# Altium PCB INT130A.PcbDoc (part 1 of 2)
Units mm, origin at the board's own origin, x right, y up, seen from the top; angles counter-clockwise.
Board outline 103.68 x 57.35 mm, 2 copper layers (Top Layer, Bottom Layer), stack 1.575 mm thick; 110 components, 45 nets, 213 pads, 183 vias.
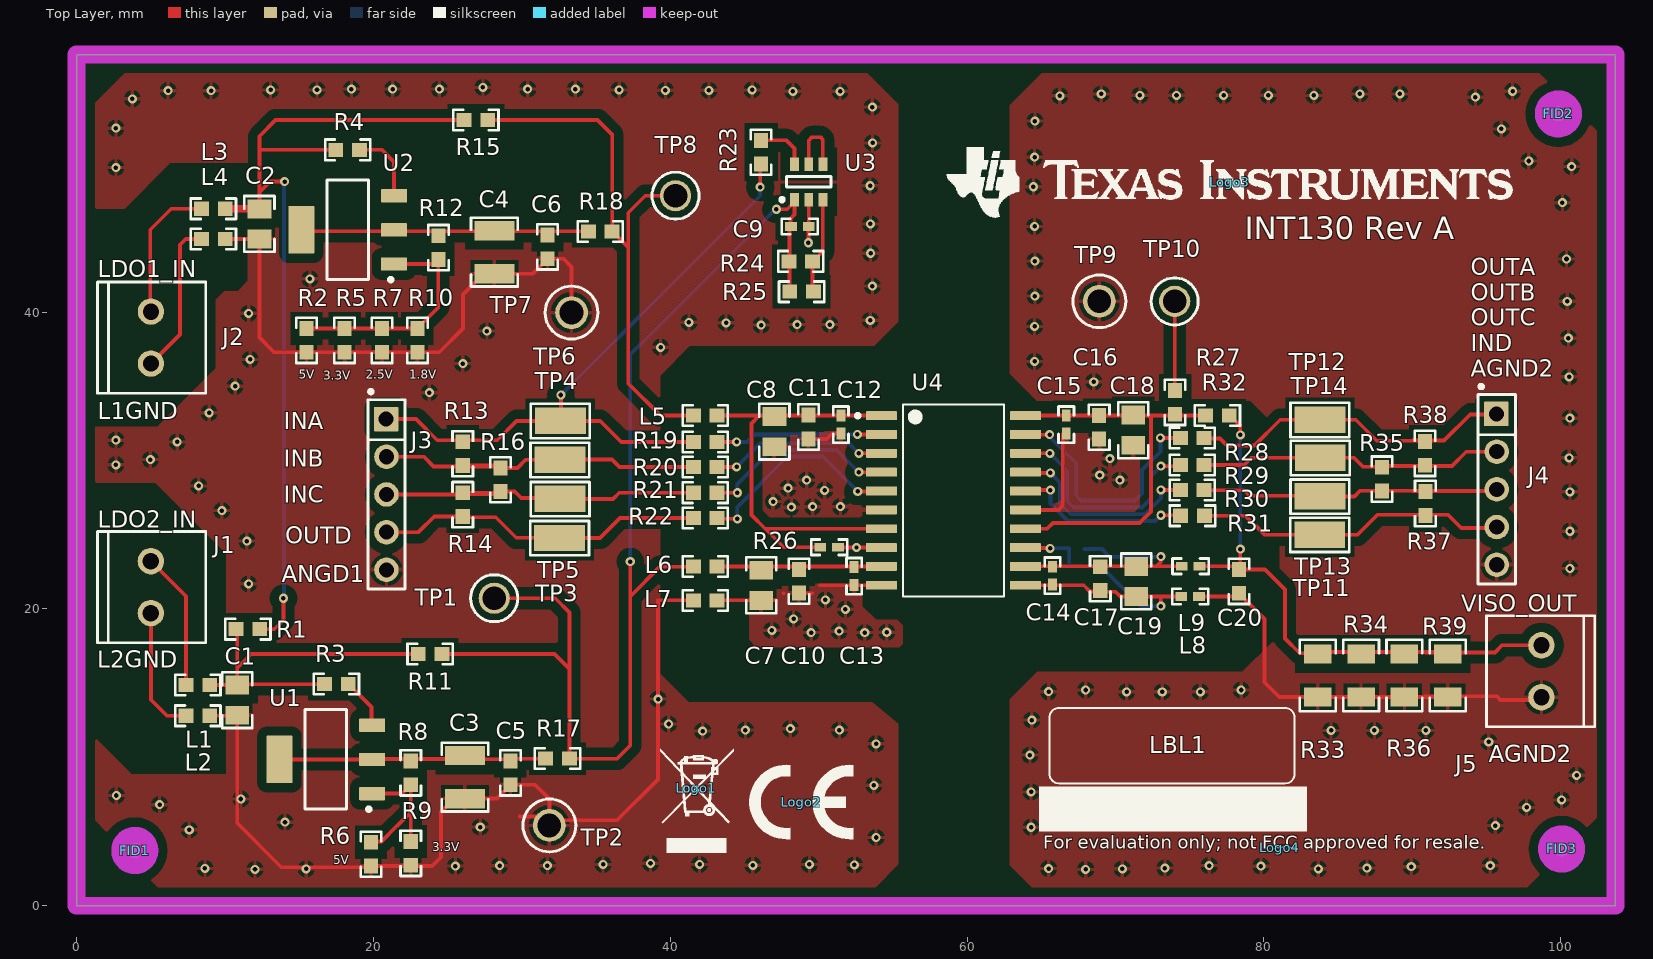
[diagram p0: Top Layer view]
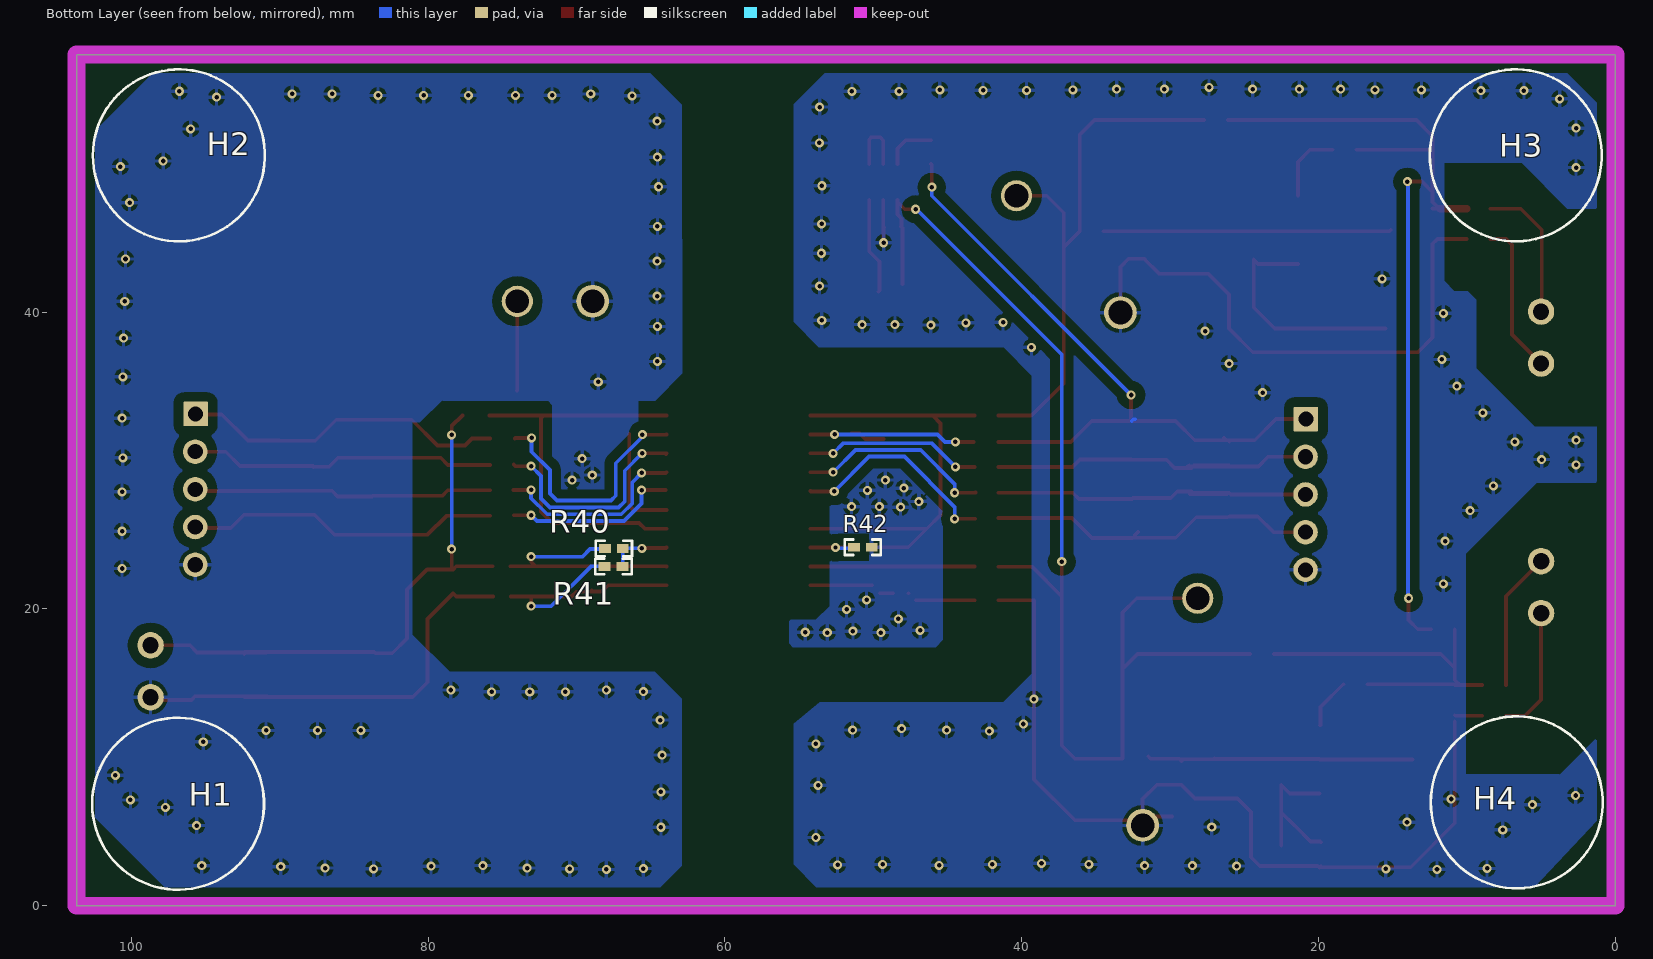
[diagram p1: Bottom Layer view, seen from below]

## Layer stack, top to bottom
Top Solder: solder mask 0.0102, Solder Resist, Dk 3.5
Top Layer: signal copper 0.0356
Dielectric1: core 1.5037, FR-4, Dk 4.8
Bottom Layer: signal copper 0.0356
Bottom Solder: solder mask 0.0102, Solder Resist, Dk 3.5

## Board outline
0,0 0,57.348 103.678,57.348 103.678,0

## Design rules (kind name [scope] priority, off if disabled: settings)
AcuteAngle [All] p1: minimum=4.50000000000000E+0001 checktracksonly=FALSE
AssemblyTestPointUsage [All] p1: valid=2
Clearance Clearance_Keepouts [((IsTrack Or IsArc) And Not InPoly) And IsFree and IsKeepOut vs ((IsTrack Or IsArc) And Not InPoly) And IsFree and IsKeepOut] p1: gap=0 ignorepadtopadclearanceinfootprint=FALSE
Clearance Clearance_BoardEdge_MountingHoles [OnCopper and InComponentClass('Mounting Holes') vs IsKeepOut] p2: gap=1.016 ignorepadtopadclearanceinfootprint=FALSE except(0: Arc-Hole Track-Hole SMDPad-Hole THPad-Hole Via-Hole Fill-Hole Poly-Hole Region-Hole Text-Hole)
Clearance Clearance_BoardEdge_Poly [OnCopper and InPoly vs IsKeepOut] p3: gap=0.635 ignorepadtopadclearanceinfootprint=FALSE except(0: Arc-Hole Track-Hole SMDPad-Hole THPad-Hole Via-Hole Fill-Hole Poly-Hole Region-Hole Text-Hole)
Clearance Clearance_BoardEdge [OnCopper and Not InComponentClass('Logo') and not InComponentClass('FiducialMark') and not InRegion(1000,500,4000,800) and Not IsKeepout vs IsKeepOut] p4: gap=0.762 ignorepadtopadclearanceinfootprint=FALSE except(0: Arc-Hole Track-Hole SMDPad-Hole THPad-Hole Via-Hole Fill-Hole Poly-Hole Region-Hole Text-Hole)
Clearance Clearance_Poly [InPolygon] p5: gap=0.635 ignorepadtopadclearanceinfootprint=FALSE except(0: Arc-Hole Track-Hole SMDPad-Hole THPad-Hole Via-Hole Fill-Hole Poly-Hole Region-Hole Text-Hole)
Clearance [All] p6: gap=0.2 ignorepadtopadclearanceinfootprint=FALSE except(0: Arc-Hole Track-Hole SMDPad-Hole THPad-Hole Via-Hole Fill-Hole Poly-Hole Region-Hole Text-Hole)
ComponentClearance ComponentClearance_MountingHoles_FiducialMarks [InComponentClass('Mounting Holes') vs InComponentClass('FiducialMark')] p1: gap=1.27 collisioncheckmode=3 verticalgap=0.254 showdistances=FALSE
ComponentClearance ComponentClearance_Shunt [InComponentClass('Header') vs InComponentClass('Shunt')] p2: gap=0 collisioncheckmode=3 verticalgap=0 showdistances=FALSE
ComponentClearance ComponentClearance_Logo [InComponentClass('Logo')] p3: gap=1.27 collisioncheckmode=3 verticalgap=0.254 showdistances=FALSE
ComponentClearance ComponentClearance_ScrewToNut [(HasFootprint('NY PMS 440 0025 PH')) vs (HasFootprint('Keystone_1902C'))] p4: gap=0.127 collisioncheckmode=3 verticalgap=0.254 showdistances=FALSE
ComponentClearance ComponentClearance_MountingHoles [InComponentClass('Mounting Holes')] p5: gap=6.35 collisioncheckmode=3 verticalgap=2540 showdistances=FALSE
ComponentClearance ComponentClearance_SmallPassives [HasFootprint('0201*') or HasFootprint('0402*') or HasFootprint('0508') or HasFootprint('0603*') or HasFootprint('0612') or HasFootprint('0805*') or HasFootprint('0815*') or HasFootprint('0830*') or HasFootprint('1206*') or HasFootprint('1210*') or HasFootprint('1808*') or HasFootprint('1812*') or HasFootprint('1825*') or HasFootprint('2010*') or HasFootprint('2220*') or HasFootprint('2225*') or HasFootprint('2512*') or HasFootprint('2728*') or HasFootprint('3518*') vs HasFootprint('0201*') or HasFootprint('0402*') or HasFootprint('0508') or HasFootprint('0603*') or HasFootprint('0612') or HasFootprint('0805*') or HasFootprint('0815*') or HasFootprint('0830*') or HasFootprint('1206*') or HasFootprint('1210*') or HasFootprint('1808*') or HasFootprint('1812*') or HasFootprint('1825*') or HasFootprint('2010*') or HasFootprint('2220*') or HasFootprint('2225*') or HasFootprint('2512*') or HasFootprint('2728*') or HasFootprint('3518*')] p6: gap=0.508 collisioncheckmode=3 verticalgap=0.254 showdistances=FALSE
ComponentClearance ComponentClearance_THtoSMT [IsThruComponent vs IsSMTComponent] p7: gap=1.016 collisioncheckmode=3 verticalgap=0.762 showdistances=FALSE
ComponentClearance ComponentClearance_THtoTH [IsThruComponent vs IsThruComponent] p8: gap=1.016 collisioncheckmode=3 verticalgap=0.762 showdistances=FALSE
ComponentClearance [All] p9: gap=1.016 collisioncheckmode=3 verticalgap=0.254 showdistances=FALSE
DiffPairsRouting [All] p1: maxlimit=2.54 minlimit=0.254 mostfreqgap=0.254 toplayer_minwidth=0.381 toplayer_maxwidth=0.381 toplayer_prefwidth=0.381 bottomlayer_minwidth=0.381 bottomlayer_maxwidth=0.381 bottomlayer_prefwidth=0.381 maxuncoupledlength=25.4
FabricationTestPointUsage TestPointUsage [All] p1: valid=2 allowmultiple=FALSE
FabricationTestpoint Testpoint [All] p1: side=3 testpointundercomponent=TRUE minsize=1.016 maxsize=2.54 preferedsize=1.524 minholesize=0 maxholesize=1.016 preferedholesize=0.813 testpointgrid=0.025 allowsidetop=TRUE allowsidebottom=TRUE usegrid=TRUE gridtolerance=0
FanoutControl Fanout_LCC [IsLCC] p1: bgadir=Out bgaviamode=Centered fanoutstyle=Auto fanoutdirection=Alternating viagrid=0.025 // Fanout_LCC (Default Rule)
FanoutControl Fanout_BGA [IsBGA] p2: bgadir=Out bgaviamode=Centered fanoutstyle=Auto fanoutdirection=Alternating viagrid=0.025 // Fanout_BGA (Default Rule)
FanoutControl Fanout_Default [All] p4: bgadir=Out bgaviamode=Centered fanoutstyle=Auto fanoutdirection=Alternating viagrid=0.025 // Fanout_Default (Default Rule)
FanoutControl Fanout_Small [(CompPinCount < 5)] p5: bgadir=Out bgaviamode=Centered fanoutstyle=Auto fanoutdirection=OutThenIn viagrid=0.025 // Fanout_Small (Default Rule)
HoleSize [All] p1: absolutevalues=TRUE maxlimit=6.375 minlimit=0.203 maxpercent=80.000 minpercent=20.000
MinimumAnnularRing MinimumAnnularRing_ThermalPadVias [IsVia and InAnyComponent] p1: minimumring=0.15
MinimumAnnularRing [All] p2: minimumring=0.152
MinimumSolderMaskSliver MinimumSolderMaskSliver_Logo [InComponentClass('Logo') vs InComponentClass('Logo')] p1: minsoldermaskwidth=0.018
MinimumSolderMaskSliver [All] p2: minsoldermaskwidth=0.1
PlaneConnect [All] p1: planeconnectstyle=Relief reliefexpansion=0.254 reliefentries=4 reliefconductorwidth=0.254 reliefairgap=0.254
PolygonConnect [All] p1: connectstyle=Relief reliefconductorwidth=0.254 reliefentries=4 polygonreliefangle="90 Angle" airgapwidth=0.254
RoutingVias ThermalPadVias [IsVia and InAnyComponent] p1: holewidth=0.305 width=0.5 viastyle="Through Hole" minholewidth=0.305 minwidth=0.483 maxholewidth=0.33 maxwidth=0.762
RoutingVias [All] p2: holewidth=0.406 width=0.864 viastyle="Through Hole" minholewidth=0.2 minwidth=0.559 maxholewidth=1.016 maxwidth=1.651
SilkToBoardRegionClearance [Not ((IsComment or IsDesignator) And (Hide <> 'False')) and not InRegion(1000,500,4000,800)] p1:
SilkToSilkClearance SilkToSilkClearance_Pb-FreeLogo [(HasFootprint('Pb-Free_Overlay_Medium') OR HasFootprint('Pb-Free_Overlay_Small')) vs (HasFootprint('Pb-Free_Overlay_Medium') OR HasFootprint('Pb-Free_Overlay_Small'))] p1: silktosilkclearance=0
SilkToSilkClearance [All] p2: silktosilkclearance=0.127
SilkToSolderMaskClearance "Silk to Solder Mask Opening" [All] p1: minsilkscreentomaskgap=0.076 clearancetoexposedcopper=FALSE
SolderMaskExpansion [All] p1: expansion=0.05
Width [All] p1: maxlimit=2.54 minlimit=0.152 preferedwidth=0.254 checkconnectedcopper=TRUE
15 further rules are at their usual default settings.

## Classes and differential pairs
component class Label: LBL1
component class AssemblyNote: ZZ1 ZZ2 ZZ3 ZZ4
component class FiducialMark: FID1 FID2 FID3
component class INT130A_Hardware: FID1 FID2 FID3 H1 H2 H3 H4 LBL1 Logo1 Logo2 Logo3 Logo4 ZZ1 ZZ2 ZZ3 ZZ4
component class Logo: Logo3
component class Header: J3 J4
component class INT130A_EVM: C1 C2 C3 C4 C5 C6 C7 C8 C9 C10 C11 C12 C13 C14 C15 C16 C17 C18 C19 C20 CL3 CR3 J1 J2 J3 J4 J5 L1 L2 L3 L4 L5 L6 L7 L8 L9 R1 R2 R3 R4 R5 R6 R7 R8 R9 R10 R11 R12 R13 R14 R15 R16 R17 R18 R19 R20 R21 R22 R23 R24 R25 R26 R27 R28 R29 R30 R31 R32 R33 R34 R35 R36 R37 R38 R39 R40 R41 R42 TP1 TP2 TP3 TP4 TP5 TP6 TP7 TP8 TP9 TP10 TP11 TP12 TP13 TP14 U1 U2 U3 U4

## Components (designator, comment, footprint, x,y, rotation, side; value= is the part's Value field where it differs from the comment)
C1 "GRM21BR6YA106KE43L" 0805_HV 10.819,13.854 r270 top value=10uF
C2 "GRM21BR6YA106KE43L" 0805_HV 12.315,45.94 r270 top value=10uF
C3 "CL32A476KOJNNNE" 1210_270 26.16,8.669 r270 top value=47uF
C4 "CL32A476KOJNNNE" 1210_270 28.144,44.04 r270 top value=47uF
C5 "CL10A105KA8NNNC" 0603 29.228,8.953 r270 top value=1uF
C6 "CL10A105KA8NNNC" 0603 31.726,44.39 r270 top value=1uF
C7 "GRM21BR6YA106KE43L" 0805_HV 46.125,21.594 r270 top value=10uF
C8 "GRM21BR6YA106KE43L" 0805_HV 47.013,31.946 r270 top value=10uF
C9 "CL05B104KO5NNNC" 0402 48.727,45.768 r0 top value=0.1uF
C10 "CL10A105KA8NNNC" 0603 48.665,21.863 r270 top value=1uF
C11 "CL10A105KA8NNNC" 0603 49.304,32.255 r270 top value=1uF
C12 "CL05B104KO5NNNC" 0402 51.49,32.424 r270 top value=0.1uF
C13 "0402B103K500CT" 0402 52.39,22.213 r90 top value=0.01uF
C14 "0402B103K500CT" 0402 65.744,22.244 r270 top value=0.01uF
C15 "CL05B104KO5NNNC" 0402 66.679,32.424 r270 top value=0.1uF
C16 "CL10A105KA8NNNC" 0603 68.896,32.244 r270 top value=1uF
C17 "CL10A105KA8NNNC" 0603 68.972,22.038 r270 top value=1uF
C18 "GRM21BR6YA106KE43L" 0805_HV 71.195,32.043 r270 top value=10uF
C19 "GRM21BR6YA106KE43L" 0805_HV 71.398,21.851 r270 top value=10uF
C20 "CL10A105KA8NNNC" 0603 78.318,21.86 r270 top value=1uF
FID1 "Fiducial" Fiducial10-30 3.92,3.722 r0 top
FID2 "Fiducial" Fiducial10-30 99.836,53.355 r90 top
FID3 "Fiducial" Fiducial10-30 100.055,3.825 r90 top
H1 "SJ-5303 (CLEAR)" Bumpon_SJ5003Transparent 96.842,6.873 r180 bottom
H2 "SJ-5303 (CLEAR)" Bumpon_SJ5003Transparent 96.788,50.561 r180 bottom
H3 "SJ-5303 (CLEAR)" Bumpon_SJ5003Transparent 6.71,50.561 r180 bottom
H4 "SJ-5303 (CLEAR)" Bumpon_SJ5003Transparent 6.646,6.969 r180 bottom
J1 "1751248" CONN_1751248 5.003,21.468 r270 top
J2 "1751248" CONN_1751248 5.008,38.282 r270 top
J3 "TSW-105-07-G-S" TSW-105-07-X-S 20.876,27.713 r270 top
J4 "TSW-105-07-G-S" TSW-105-07-X-S 95.687,28.056 r270 top
J5 "1751248" CONN_1751248 98.696,15.799 r90 top
L1 "BLM18HE152SN1D" 0603 8.169,14.87 r0 top value="1500 ohm"
L2 "BLM18HE152SN1D" 0603 8.169,12.799 r0 top value="1500 ohm"
L3 "BLM18HE152SN1D" 0603 9.218,46.966 r0 top value="1500 ohm"
L4 "BLM18HE152SN1D" 0603 9.218,44.924 r0 top value="1500 ohm"
L5 "BLM18HE152SN1D" 0603 42.358,33.024 r0 top value="1500 ohm"
L6 "BLM18HE152SN1D" 0603 42.358,22.849 r0 top value="1500 ohm"
L7 "BLM18HE152SN1D" 0603 42.358,20.578 r0 top value="1500 ohm"
L8 "BLM15EX331SN1D" 0402 75.031,20.844 r0 top value="330 ohm"
L9 "BLM15EX331SN1D" 0402 75.06,22.873 r0 top value="330 ohm"
LBL1 "Size: 0.65\" x 0.20 \"" Label_650x200 73.81,10.785 r0 top
Logo1 "WEEE logo" WEEE_Minimum 41.756,7.93 r0 top
Logo2 "CE Mark" CE_Mark_5mm 48.833,6.985 r0 top
Logo3 "Texas Instruments" TI_Horizontal_Overlay_Medium 77.684,48.732 r0 top
Logo4 "FCC disclaimer" FCC_disclaimer 81.05,3.895 r0 top
R1 "DNP" 0603 11.544,18.635 r0 top value=0
R2 "RC0603FR-07732RL" 0603 15.488,38.089 r90 top value=732
R3 "RC0603JR-070RL" 0603 17.507,14.931 r0 top value=0
R4 "RC0603JR-070RL" 0603 18.264,50.933 r0 top value=0
R5 "DNP" 0603 18.059,38.089 r90 top value=390
R6 "RC0603FR-07732RL" 0603 19.833,3.475 r90 top value=732
R7 "DNP" 0603 20.571,38.089 r90 top value=240
R8 "RC0603FR-07240RL" 0603 22.515,8.953 r90 top value=240
R9 "DNP" 0603 22.515,3.526 r90 top value=390
R10 "DNP" 0603 22.958,38.089 r90 top value=102
R11 "DNP" 0603 23.821,16.963 r0 top value=0
R12 "RC0603FR-07240RL" 0603 24.373,44.34 r90 top value=240
R13 "DNP" 0603 26.019,30.459 r90 top value=0
R14 "DNP" 0603 26.019,27.028 r90 top value=0
R15 "DNP" 0603 26.9,52.94 r0 top value=0
R16 "DNP" 0603 28.559,28.703 r90 top value=0
R17 "RC0603JR-070RL" 0603 32.403,9.912 r0 top value=0
R18 "RC0603JR-070RL" 0603 35.282,45.44 r0 top value=0
R19 "RC0603FR-071KL" 0603 42.358,31.254 r0 top value=1.00k
R20 "RC0603FR-071KL" 0603 42.358,29.569 r0 top value=1.00k
R21 "RC0603FR-071KL" 0603 42.358,27.83 r0 top value=1.00k
R22 "RC0603FR-071KL" 0603 42.358,26.129 r0 top value=1.00k
R23 "DNP" 0603 46.121,50.772 r90 top value=0
R24 "RC0603FR-0740K2L" 0603 48.79,43.421 r180 top value=40.2k
R25 "DNP" 0603 48.848,41.375 r180 top value=40.2k
R26 "RC0402FR-071KL" 0402 50.705,24.156 r0 top value=1.00k
R27 "RC0603JR-070RL" 0603 74.01,33.916 r90 top value=0
R28 "RC0603FR-071KL" 0603 75.166,31.522 r0 top value=1.00k
R29 "RC0603FR-071KL" 0603 75.166,29.688 r0 top value=1.00k
R30 "RC0603FR-071KL" 0603 75.166,28.019 r0 top value=1.00k
R31 "RC0603FR-071KL" 0603 75.183,26.28 r0 top value=1.00k
R32 "RC0603JR-070RL" 0603 76.859,33.041 r0 top value=0
R33 "DNP" 1206 83.62,15.513 r90 top value=0
R34 "DNP" 1206 86.541,15.513 r90 top value=0
R35 "DNP" 0603 87.965,28.744 r90 top value=0
R36 "DNP" 1206 89.462,15.513 r90 top value=0
R37 "DNP" 0603 90.873,27.105 r90 top value=0
R38 "DNP" 0603 90.859,30.483 r90 top value=0
R39 "DNP" 1206 92.383,15.513 r90 top value=0
R40 "RC0402JR-070RL" 0402 67.48,24.082 r0 bottom value=0
R41 "DNP" 0402 67.505,22.868 r0 bottom value=0
R42 "DNP" 0402 50.705,24.156 r0 bottom value=1.00k
TP1 "5010" KSTN-5010_V 28.137,20.719 r0 top
TP2 "5011" Keystone5011 31.853,5.414 r0 top
TP3 "5015" Testpoint_Keystone_Miniature 32.539,24.782 r0 top
TP4 "5015" Testpoint_Keystone_Miniature 32.561,30.049 r0 top
TP5 "5015" Testpoint_Keystone_Miniature 32.572,27.412 r0 top
TP6 "5015" Testpoint_Keystone_Miniature 32.59,32.669 r0 top
TP7 "5011" Keystone5011 33.347,39.965 r0 top
TP8 "5010" KSTN-5010_V 40.353,47.84 r0 top
TP9 "5011" Keystone5011 68.911,40.727 r0 top
TP10 "5010" KSTN-5010_V 73.986,40.727 r0 top
TP11 "5015" Testpoint_Keystone_Miniature 83.76,25.006 r0 top
TP12 "5015" Testpoint_Keystone_Miniature 83.77,32.746 r0 top
TP13 "5015" Testpoint_Keystone_Miniature 83.77,27.58 r0 top
TP14 "5015" Testpoint_Keystone_Miniature 83.79,30.182 r0 top
U1 "LM317MDCY" DCY0004A_N 16.788,9.859 r180 top
U2 "LM317MDCY" DCY0004A_N 18.264,45.54 r180 top
U3 "LTC6908HS6-1#TRMPBF" LT-S6-6-SOT-23_L 49.327,48.773 r90 top
U4 "ISOW7741DFM" DFM0020A-MFG 59.079,27.309 r0 top
ZZ1 "This Assembly Note is for PCB labels only" AssemblyNoteLabel -2.561,100.295 r0 top
ZZ2 "These assemblies are ESD sensitive, ESD precautions shall be observed." AssemblyNote -2.561,97.529 r0 top
ZZ3 "These assemblies must be clean and free from flux and all contaminants. Use of no clean flux is not acceptable." AssemblyNote -2.561,95.28 r0 top
ZZ4 "These assemblies must comply with workmanship standards IPC-A-610 Class 2, unless otherwise specified." AssemblyNote -2.561,93.03 r0 top

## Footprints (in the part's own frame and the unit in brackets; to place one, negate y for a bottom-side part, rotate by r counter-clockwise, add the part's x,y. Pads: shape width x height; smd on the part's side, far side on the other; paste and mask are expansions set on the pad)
0402 [mm] "0402 from SM-752 data"
  rect 0.8x0.6 smd: 1(-0.6,0) 2(0.6,0)
  silkscreen extent -1.22,-0.52 1.22,0.52, body extent -0.55,-0.3 0.55,0.3, height 0.6
0603 [mm] "0603 from SM-752 data"
  rect 1x0.95 smd: 1(-0.8,0) 2(0.8,0)
  silkscreen extent -1.52,-0.69 1.52,0.69, body extent -0.87,-0.47 0.87,0.47, height 1
0805_HV [mil] "0805 with 30mil clearance between pads"
  rect 50x63 smd: 1(-40,0) 2(40,0)
  silkscreen extent -74,-40 74,40, body extent -43,-29 43,29, height 57
1206 [mm] "1206 from SM-752 data"
  rect 1.3x1.85 smd: 1(-1.45,0) 2(1.45,0)
  silkscreen extent -2.4,-1.21 2.4,1.21, body extent -1.7,-0.9 1.7,0.9, height 1.35
1210_270 [mm] "1210"
  rect 1.3x2.7 smd: 1(-1.45,0) 2(1.45,0)
  silkscreen extent -2.32,-1.57 2.32,1.57, body extent -1.7,-1.35 1.7,1.35, height 2.7
AssemblyNote [mm] "Assembly Note"
AssemblyNoteLabel [mm] "Assembly Note for PCB Labels"
Bumpon_SJ5003Transparent [mil] "3M Hemispherical Bumpon transparent"
  round 1 on Mech4: 0(0,0)
  silkscreen extent -228,-228 228,228, body extent -219,-219 219,219, height 197
CE_Mark_5mm [mm] "Minimum text height for CE Mark"
  silkscreen extent -3.5,-2.5 3.5,2.5
CONN_1751248 [mm] "Phoenix Contact"
  round 1.778 hole 1.1: 1(-1.75,0) 2(1.75,0)
  silkscreen extent -3.75,-3.6 3.75,3.7, body extent -3.75,-3.6 3.75,3.7, height 8.52
DCY0004A_N [mm] "SOT223/SC73, 4-Leads, Body 6.5x3.5mm, Pitch 2.3mm, Lead Span 7mm, IPC Medium Density"
  rrect11% 1.75x0.9 smd: 1(-3.125,2.3) 2(-3.125,0) 3(-3.125,-2.3)
  rrect6% 1.75x3.2 smd: 4(3.125,0)
  silkscreen extent -3.03,-3.35 1.4,3.47, body extent -3.48,-3.25 3.48,3.25, height 1.68
DFM0020A-MFG [mm]
  rrect17% 2.1x0.6 smd paste+0 mask+0: 1(-4.85,5.715) 2(-4.85,4.445) 3(-4.85,3.175) 4(-4.85,1.905) 5(-4.85,0.635) 6(-4.85,-0.635) 7(-4.85,-1.905) 8(-4.85,-3.175) 9(-4.85,-4.445) 10(-4.85,-5.715) 11(4.85,-5.715) 12(4.85,-4.445) 13(4.85,-3.175) 14(4.85,-1.905) 15(4.85,-0.635) 16(4.85,0.635) 17(4.85,1.905) 18(4.85,3.175) 19(4.85,4.445) 20(4.85,5.715)
  silkscreen extent -6.57,-6.47 3.4,6.47, body extent -6,-6.72 6,6.72, height 0.25
FCC_disclaimer [mm]
Fiducial10-30 [mm]
  round 1 smd mask+1: 1(0,0)
  Top Layer keep-out circle w1.678: c0,0 r0.75
Keystone5011 [mil] "Keystone Multipurpose loops"
  round 87 hole 63: 1(0,0)
  silkscreen extent -70,-70 70,70, body extent -63,-63 63,62, height 319
KSTN-5010_V [mm] "Test Point, Dia 3.17mm"
  round 2.1 hole 1.6: 1(0,0)
  silkscreen extent -1.59,-1.58 1.59,1.58, body extent -1.59,-1.59 1.59,1.59, height 8.13
Label_650x200 [mm] "Thermal Transfer Label"
  silkscreen extent -8.25,-2.54 8.25,2.54, body extent -8.26,-2.54 8.26,2.54, height 0.03
LT-S6-6-SOT-23_L [mm] "SOT23, 6-Leads, Body 3x1.75mm, Pitch 0.95mm, IPC High Density"
  rect 0.9x0.6 smd: 1(-1.2,0.95) 2(-1.2,0) 3(-1.2,-0.95) 4(1.2,-0.95) 5(1.2,0) 6(1.2,0.95)
  silkscreen extent -1.32,-1.5 0.35,1.92, body extent -0.87,-1.5 0.87,1.5, height 1.45
Testpoint_Keystone_Miniature [mil] "Miniature SMT test point"
  rect 135x70 smd: 1(0,0)
  silkscreen extent -78,-46 78,45, body extent -52,-20 52,20, height 61
TI_Horizontal_Overlay_Medium [mm]
  silkscreen extent -19.06,-2.37 19.06,2.37
TSW-105-07-X-S [mm] "Samtec 100mil, 1x5, 230 mil above insulator"
  rrect6% 1.65x1.65 hole 1.016: 1(-5.08,-0.025)
  round 1.65 hole 1.016: 2(-2.54,0) 3(0,0) 4(2.54,0) 5(5.08,0)
  silkscreen extent -7.05,-1.25 6.37,1.25, body extent -6.35,-1.27 6.35,1.27, height 8.38
WEEE_Minimum [mm] "WEEElie bin"
  silkscreen extent -2.42,-4.38 2.52,2.65

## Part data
C1 C2 C7 C8 C18 C19: library part CMP-0008310-2, "CAP, CERM, 10 uF, 35 V, +/- 10%, X5R, 0805", Cap_Case=0805, Manufacturer=MuRata, Supplier Part Number 1=490-10514-1-ND, TempCo=X5R, Tolerance_%=10%, Value1=Unknown, Value2=35V, ValueDisplayed=10uF
C3 C4: library part CMP-0082097-1, "CAP, CERM, 47 µF, 16 V,+/- 10%, X5R, 1210", Cap_Case=1210, Manufacturer="Samsung Electro-Mechanics", Supplier Part Number 1=1276-3376-2-ND, TempCo=X5R, Tolerance_%=10%, Value1="0.001 ohm", Value2=16V, ValueDisplayed=47µF
C5 C6 C10 C11 C16 C17 C20: library part CMP-0007350-5, "CAP, CERM, 1 uF, 50 V, +/- 10%, X5R, 0603", Cap_Case=0603, Manufacturer="Samsung Electro-Mechanics", Supplier Part Number 1=1276-1102-6-ND, TempCo=X5R, Tolerance_%=10%, Value1=Unknown, Value2=25V, ValueDisplayed=1uF
C9 C12 C15: library part CMP-0085850-1, "CAP, CERM, 0.1 µF, 16 V,+/- 10%, X7R, 0402", Cap_Case=0402, Manufacturer=Walsin, TempCo=X7R, Tolerance_%=10%, Value2=16V, ValueDisplayed=0.1µF
C13 C14: library part CMP-0085842-1, "CAP, CERM, 0.01 µF, 50 V,+/- 10%, X7R, 0402", Cap_Case=0402, Manufacturer=Walsin, TempCo=X7R, Tolerance_%=10%, Value2=50V, ValueDisplayed=0.01µF
FID1 FID2 FID3: library part CMP-0077181-1, "Fiducial mark.  There is nothing to buy or mount.", Manufacturer=N/A
H1 H2 H3 H4: library part CMP-0003620-1, "Bumpon, Hemisphere, 0.44 X 0.20, Clear", Manufacturer=3M, Supplier Part Number 1=SJ5303-7-ND
J1 J2 J5: library part CMP-0055473-1, "Conn Term Block, 2POS, 3.5mm, TH", Manufacturer="Phoenix Contact", Supplier Part Number 1=277-5719-ND
J3 J4: library part CMP-0075411-1, "Header, 100mil, 5x1, Gold, TH", Color=Black, Current_A=6.3A, Manufacturer=Samtec, Supplier Part Number 1=SAM1029-05-ND, Voltage_V=550V
L1 L2 L3 L4 L5 L6 L7: library part CMP-0003349-2, "Ferrite Bead, 1500 ohm @ 100 MHz, 0.5 A, 0603", Manufacturer=MuRata, Supplier Part Number 1=490-5216-1-ND, Value1="0.5 ohm", Value2=0.5A, ValueDisplayed="1500 ohm"
L8 L9: library part CMP-0003421-1, "Ferrite Bead, 330 ohm @ 100 MHz, 1.1 A, 0402", Manufacturer=MuRata, Value1="0.28 ohm", Value2=1.1A, ValueDisplayed="330 ohm"
LBL1: library part THT-14-423-10, "Thermal Transfer Printable Labels, 0.650\" W x 0.200\" H - 10,000 per roll", Alternate Manufacturer=-, Manufacturer=Brady, Supplier Part Number 1=2065596
Logo1: library part CMP-0074769-1
Logo2: library part CMP-0074844-1
Logo3: library part CMP-0074838-1, "Texas Instrument Corporate Signature"
Logo4: library part CMP-0074847-1, "FCC_disclaimer"
R1 R11 R13 R14 R15 R16 R23 R35 R37 R38: library part CMP-0025885-5, "RES, 0, 5%, 0.1 W, 0603", Manufacturer=Yageo, PartNumber=RC0603JR-070RL, Power_W=100mW, Supplier Part Number 1=311-0.0GRCT-ND, TempCo="200 ppm/C", Tolerance_%=5%, Value2=0.1W, Value_Code=0000, ValueDisplayed=0
R2 R6: library part CMP-0023262-5, "RES, 732, 1%, 0.1 W, 0603", Manufacturer=Yageo, Power_W=100mW, Supplier Part Number 1=311-732HRCT-ND, TempCo="100 ppm/C", Tolerance_%=1%, Value2=0.1W, Value_Code=732R, ValueDisplayed=732
R3 R4 R17 R18 R27 R32: library part CMP-0025885-5, "RES, 0, 5%, 0.1 W, 0603", Manufacturer=Yageo, Power_W=100mW, Supplier Part Number 1=311-0.0GRCT-ND, TempCo="200 ppm/C", Tolerance_%=5%, Value2=0.1W, Value_Code=0000, ValueDisplayed=0
R5 R9: library part CMP-0023069-5, "RES, 390, 1%, 0.1 W, 0603", Manufacturer=Yageo, PartNumber=RC0603FR-07390RL, Power_W=100mW, Supplier Part Number 1=311-390HRCT-ND, TempCo="100 ppm/C", Tolerance_%=1%, Value2=0.1W, Value_Code=390R, ValueDisplayed=390
R7: library part CMP-0022938-5, "RES, 240, 1%, 0.1 W, 0603", Manufacturer=Yageo, PartNumber=RC0603FR-07240RL, Power_W=100mW, Supplier Part Number 1=311-240HRCT-ND, TempCo="100 ppm/C", Tolerance_%=1%, Value2=0.1W, Value_Code=240R, ValueDisplayed=240
R8 R12: library part CMP-0022938-5, "RES, 240, 1%, 0.1 W, 0603", Manufacturer=Yageo, Power_W=100mW, Supplier Part Number 1=311-240HRCT-ND, TempCo="100 ppm/C", Tolerance_%=1%, Value2=0.1W, Value_Code=240R, ValueDisplayed=240
R10: library part CMP-0022738-5, "RES, 102, 1%, 0.1 W, 0603", Manufacturer=Yageo, PartNumber=RC0603FR-07102RL, Power_W=100mW, Supplier Part Number 1=311-102HRCT-ND, TempCo="100 ppm/C", Tolerance_%=1%, Value2=0.1W, Value_Code=102R, ValueDisplayed=102
R19 R20 R21 R22 R28 R29 R30 R31: library part CMP-0022895-5, "RES, 1.00 k, 1%, 0.1 W, 0603", Manufacturer=Yageo, Power_W=100mW, Supplier Part Number 1=311-1.00KHRCT-ND, TempCo="100 ppm/C", Tolerance_%=1%, Value2=0.1W, Value_Code=1k00, ValueDisplayed=1.00k
R24: library part CMP-0023098-5, "RES, 40.2 k, 1%, 0.1 W, 0603", Manufacturer=Yageo, Power_W=100mW, Supplier Part Number 1=311-40.2KHRCT-ND, TempCo="100 ppm/C", Tolerance_%=1%, Value2=0.1W, Value_Code=40k2, ValueDisplayed=40.2k
R25: library part CMP-0023098-5, "RES, 40.2 k, 1%, 0.1 W, 0603", Manufacturer=Yageo, PartNumber=RC0603FR-0740K2L, Power_W=100mW, Supplier Part Number 1=311-40.2KHRCT-ND, TempCo="100 ppm/C", Tolerance_%=1%, Value2=0.1W, Value_Code=40k2, ValueDisplayed=40.2k
R26: library part CMP-0026725-1, "RES, 1.00 k, 1%, 0.0625 W, 0402", Manufacturer="Yageo America", Power_W=62.5mW, Supplier Part Number 1=311-1.00KLRCT-ND, TempCo="100 ppm/C", Tolerance_%=1%, Value2=0.0625W, Value_Code=1k00, ValueDisplayed=1.00k
R33 R34 R36 R39: library part CMP-0018759-2, "RES, 0, 5%, 0.25 W, 1206", Manufacturer="Yageo America", PartNumber=RC1206JR-070RL, Power_W=250mW, Supplier Part Number 1=311-0.0ERCT-ND, TempCo="200 ppm/C", Tolerance_%=5%, Value2=0.25W, Value_Code=0000, ValueDisplayed=150
R40: library part CMP-0027004-2, "RES, 0, 5%, 0.063 W, 0402", Manufacturer="Yageo America", Power_W=63mW, Supplier Part Number 1=311-0.0JRCT-ND, TempCo="200 ppm/C", Tolerance_%=5%, Value2=0.063W, Value_Code=0000, ValueDisplayed=0
R41: library part CMP-0027004-2, "RES, 0, 5%, 0.063 W, 0402", Manufacturer="Yageo America", PartNumber=RC0402JR-070RL, Power_W=63mW, Supplier Part Number 1=311-0.0JRCT-ND, TempCo="200 ppm/C", Tolerance_%=5%, Value2=0.063W, Value_Code=0000, ValueDisplayed=0
R42: library part CMP-0026725-1, "RES, 1.00 k, 1%, 0.0625 W, 0402", Manufacturer="Yageo America", PartNumber=RC0402FR-071KL, Power_W=62.5mW, Supplier Part Number 1=311-1.00KLRCT-ND, TempCo="100 ppm/C", Tolerance_%=1%, Value2=0.0625W, Value_Code=1k00, ValueDisplayed=1.00k
TP1 TP8 TP10: library part CMP-1672-00002-3, "Test Point, Red, Through Hole, RoHS, Bulk", Colour=Red, Manufacturer=Keystone, Package Quantity=100, Supplier Part Number 1=36-5010-ND, Supplier Part Numer 2=534-5010
TP2 TP7 TP9: library part CMP-0055148-1, "Test Point, Multipurpose, Black, TH", Color=Black, Manufacturer=Keystone, Supplier Part Number 1=36-5011-ND
TP3 TP4 TP5 TP6 TP11 TP12 TP13 TP14: library part CMP-0055152-1, "Test Point, Miniature, SMT", Manufacturer=Keystone, Supplier Part Number 1=36-5015TR-ND
U1 U2: library part CMP-0065981-1, "3/4 Pin 500mA Adjustable Positive Voltage Regulator, DCY0004A (SOT-223-4)", Alternate Manufacturer="Texas Instruments"
U3: library part CMP-0475-00317-1, "Resistor Set SOT-23 Oscillator, 2.7 to 5.5 V, 6-pin SOT23 (S6-6), -40 to 85 degC, Pb-Free", Frequency(kHz)=700, Manufacturer="Linear Technology"
U4: library part CMP-0091099-2, Manufacturer="Texas Instruments", Operating Temperature Range=to
ZZ1: library part AssemblyNoteLabel, Alternate Manufacturer=-
ZZ2 ZZ3 ZZ4: library part AssemblyNote, Alternate Manufacturer=-

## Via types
v1: diameter 0.61, hole 0.305, Top Layer to Bottom Layer, tented both sides, 182 vias
v2: diameter 0.6, hole 0.254, Top Layer to Bottom Layer, tented both sides, 1 vias

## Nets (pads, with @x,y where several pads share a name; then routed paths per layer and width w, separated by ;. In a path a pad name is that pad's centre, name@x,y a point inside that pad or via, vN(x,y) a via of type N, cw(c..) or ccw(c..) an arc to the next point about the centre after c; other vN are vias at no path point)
AGND1: C1.2 C2.2 C3.2 C4.2 C5.2 C6.2 C9.2 J3.5 L2.2 L4.2 L7.1 R2.1 R5.1 R6.1 R7.1 R9.1 R10.1 TP2.1 TP7.1 U3.2 | length 102.7
  Top Layer w0.254: L2.2@8.969,12.799 10.78,12.799 C1.2@10.819,12.838 ; L4.2@10.018,44.924 11.993,44.924 12.315,44.601 12.315,38.282 13.308,37.289 R2.1@15.488,37.289 R5.1@18.059,37.289 R7.1@20.571,37.289 R10.1@22.958,37.289 24.437,37.289 26.037,38.889 26.037,41.182 27.444,42.59 C4.2@28.144,42.59 30.751,42.59 31.726,43.565 C6.2@31.726,43.59 32.797,43.59 33.347,43.04 33.347,40.714 TP7.1@33.732,40.329 ; C1.2@10.819,12.418 10.819,5.572 13.791,2.6 19.783,2.6 19.833,2.65 19.927,2.556 19.952,2.556 20.071,2.675 23.963,2.675 24.56,3.272 24.56,6.321 24.592,6.353 24.593,6.353 25.46,7.219 C3.2@26.16,7.219 28.319,7.219 29.228,8.128 C5.2@29.228,8.153 30.893,8.153 31.853,7.194 TP2.1@31.853,6.018 ; 29.861,6.018 TP2.1@31.853,6.018 ; TP2.1@31.853,5.414 TP2.1@31.853,5.755 ; L7.1@41.558,20.578 39.174,20.578 39.174,8.509 36.42,5.755 TP2.1@31.853,5.755 ; v1(49.304,44.671) 49.304,45.691 49.277,45.718 C9.2@49.327,45.768 U3.2@49.327,47.573 ; TP2.1@31.853,5.755 TP2.1@31.853,6.018
  Bottom Layer w0.254: 32.37,32.774 32.485,32.774 32.59,32.669
  other v1: 12.019,2.455 15.466,2.48 8.644,2.512 25.521,2.673 28.503,2.698 31.726,2.698 45.563,2.726 52.406,2.757 35.471,2.782 41.97,2.782 49.374,2.782 38.666,2.858 53.865,4.598 7.587,5.116 27.196,5.302 14.041,5.634 5.589,6.813 11.069,7.194 2.678,7.43 53.716,8.112 53.865,10.912 42.184,11.772 45.063,11.837 51.399,11.837 48.089,11.929 39.888,12.247 39.174,13.924 11.59,21.69 11.472,24.569 9.787,26.625 8.225,28.286 2.646,29.711 4.968,30.062 6.773,31.252 2.646,31.371 8.931,33.213 23.766,34.571 10.68,35.007 26.019,36.532 11.69,36.808 39.343,37.628 27.644,38.722 46.125,39.125 48.541,39.16 50.753,39.16 43.755,39.279 41.256,39.309 53.473,39.446 11.59,39.916 53.618,41.753 15.722,42.242 53.491,43.966 53.484,45.941 53.462,48.514 2.646,49.738 53.626,51.395 2.646,52.39 53.611,53.815 3.756,54.371 48.265,54.878 51.44,54.872 6.164,54.917 9.058,54.917 39.671,54.939 42.603,54.939 13.066,54.969 16.196,54.969 36.555,54.969 45.519,54.969 18.52,55.03 21.291,55.03 24.442,55.03 30.394,55.03 33.605,55.03 27.375,55.135
AGND2: C15.2 C16.2 C18.2 C20.2 J4.5 J5.1 L8.2 R33.1 R34.1 R36.1 R39.1 TP9.1 U4.15 | length 37.8
  Top Layer w0.254: U4.15@63.929,26.674 66.156,26.674 66.445,26.963 C15.2@66.445,31.793 ; L8.2@75.631,20.844 78.102,20.844 C20.2@78.318,21.06 78.318,21.035 80.029,19.323 80.029,15.065 81.031,14.063 R33.1@83.62,14.063 R34.1@86.541,14.063 R36.1@89.462,14.063 R39.1@92.383,14.063 ; 90.859,14.115 95.695,14.115 95.938,13.871 98.335,13.871 J5.1@98.696,13.51
  other v1: 67.991,2.449 70.456,2.485 83.665,2.485 65.494,2.506 73.329,2.539 86.941,2.539 89.924,2.633 79.799,2.667 76.31,2.709 95.246,2.703 64.306,5.289 95.592,5.406 97.697,6.622 100.055,7.127 64.306,7.669 101.071,8.789 64.235,10.152 95.145,11.042 84.52,11.811 87.441,11.811 90.914,11.811 64.357,12.514 65.494,14.422 70.748,14.411 73.147,14.411 75.711,14.411 67.991,14.538 78.465,14.538 100.614,22.723 100.614,25.232 100.614,27.887 70.293,28.682 68.935,29.019 69.612,30.124 100.563,30.182 100.614,32.852 68.533,35.304 100.563,35.636 64.546,36.674 100.513,38.242 64.546,39.033 100.436,40.727 64.572,41.081 64.572,43.439 100.386,43.576 64.546,45.768 100.11,47.371 64.47,48.444 100.731,49.808 97.85,50.18 64.546,50.437 95.991,52.343 64.572,52.869 94.246,54.478 66.248,54.569 71.645,54.605 74.108,54.605 77.284,54.605 80.294,54.605 83.368,54.597 69.038,54.696 86.466,54.696 89.159,54.696 96.753,54.881
DATA: J3.1 R13.2 R19.1 R23.1 TP6.1 | length 45.6
  Top Layer w0.254: J3.1@20.85,32.793 22.871,32.793 24.293,31.371 R13.2@26.131,31.371 ; R13.2@26.019,31.259 R13.2@26.131,31.371 ; R13.2@26.304,31.45 R13.2@26.368,31.513 ; v1(32.631,34.415) 32.631,32.71 TP6.1@32.59,32.669 ; R19.1@41.558,31.254 36.698,31.254 35.282,32.669 TP6.1@32.59,32.669 ; v1(46.059,48.423) 46.059,49.91 R23.1@46.121,49.972 ; R13.2@26.131,31.371 28.344,31.371 29.643,32.669 TP6.1@32.59,32.669
  Bottom Layer w0.254: v1(32.631,34.415) 46.059,47.843 v1(46.059,48.423)
GND1: C7.2 C8.2 C10.2 C11.2 C12.2 C13.1 L7.2 R42.1 U4.6 U4.10 | length 11.4
  Top Layer w0.254: L7.2@43.158,20.578 C7.2@46.125,20.578 47.141,20.578 ; 47.613,21.049 47.649,21.049 ; C10.2@48.665,21.063 49.547,21.063 ; C11.2@49.304,31.455 50.544,31.455 50.912,31.824 C12.2@51.49,31.824 ; 50.078,21.594 U4.10@54.229,21.594
  other v1: 49.489,18.409 53.102,18.409 54.585,18.428 51.374,18.504 46.84,18.555 48.303,19.323 51.802,19.976 50.451,20.608 48.162,26.854 49.592,26.886 51.465,26.886 46.93,27.231 50.405,27.992 47.935,28.135 49.193,28.682
GND2: C14.2 C17.2 C19.2 L8.1 R41.2 U4.11 | length 17.8
  Top Layer w0.254: U4.11@63.929,21.594 65.585,21.594 67.864,21.594 68.281,21.177 68.911,21.177 C17.2@68.972,21.238 69.047,21.163 70.001,21.163 70.329,20.835 C19.2@71.398,20.835 71.407,20.844 72.797,20.844 73.049,20.844 ; v1(73.049,20.188) 73.049,20.844 ; L8.1@74.431,20.844 73.049,20.844
  Bottom Layer w0.254: R41.2@67.914,22.868 69.015,22.868 71.696,20.188 v1(73.049,20.188)
L1GND: J2.2 L4.1 | length 10.4
  Top Layer w0.254: J2.2@5.008,36.532 6.965,38.489 6.965,44.54 7.349,44.924 L4.1@8.418,44.924
L2GND: J1.2 L2.1 | length 8.7
  Top Layer w0.254: J1.2@5.003,19.718 5.003,13.882 6.086,12.799 L2.1@7.369,12.799
LDO1_IN: J2.1 L3.1 | length 9.6
  Top Layer w0.254: J2.1@5.008,40.032 4.958,40.082 4.958,45.551 6.372,46.966 L3.1@8.418,46.966
LDO2_IN: J1.1 L1.1 | length 9.3
  Top Layer w0.254: J1.1@5.003,23.218 7.369,20.851 L1.1@7.369,14.87
NetC1_1: C1.1 L1.2 R1.1 R3.1 R11.1 | length 24.2
  Top Layer w0.254: L1.2@8.969,14.87 C1.1@10.477,14.87 ; C1.1@10.819,14.87 C1.1@10.477,14.87 ; C1.1@10.819,14.931 R3.1@16.707,14.931 ; R1.1@10.819,18.635 10.819,16.02 ; R11.1@23.021,16.963 11.761,16.963 10.819,16.02 ; C1.1@10.477,14.87 10.819,15.212 10.819,16.02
